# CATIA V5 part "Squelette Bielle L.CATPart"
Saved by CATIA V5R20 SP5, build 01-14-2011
Part number: Squelette Bielle L
Publications: "Droite.1", "Droite.2", "Droite.3", "Plan.1", "Droite.4", "Droite.5"
Bounding box of the stored display mesh (mm): x -100 to 0, y -50 to 0, z -30 to 30
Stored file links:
  U:\CFAO\Thinkmotion\Squelette Bielle L.CATPart
  U:\CFAO\Thinkmotion\Bras Articule.CATProduct
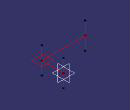
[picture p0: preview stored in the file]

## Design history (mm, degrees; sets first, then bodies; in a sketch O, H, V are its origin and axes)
Set1
  Line1: type Normal, RefPoint Point1, RefSkin xy-plane, Start -30, End 30
  Line2: type Normal, RefPoint Point2, RefSkin xy-plane, Start -30, End 30
  Line3: type Normal, RefPoint Point3, RefSkin xy-plane, Start -30, End 30
  Plane1: type 3Points, Element1 Point1, Element2 Point2, Element3 Point3
  Line4: type PtPt, FirstPoint Point3, SecondPoint Point2
  Line5: type PtPt, FirstPoint Point1, SecondPoint Point2
Set2
  Point1 to Point3: linked copy from another document
Body1 (main body)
